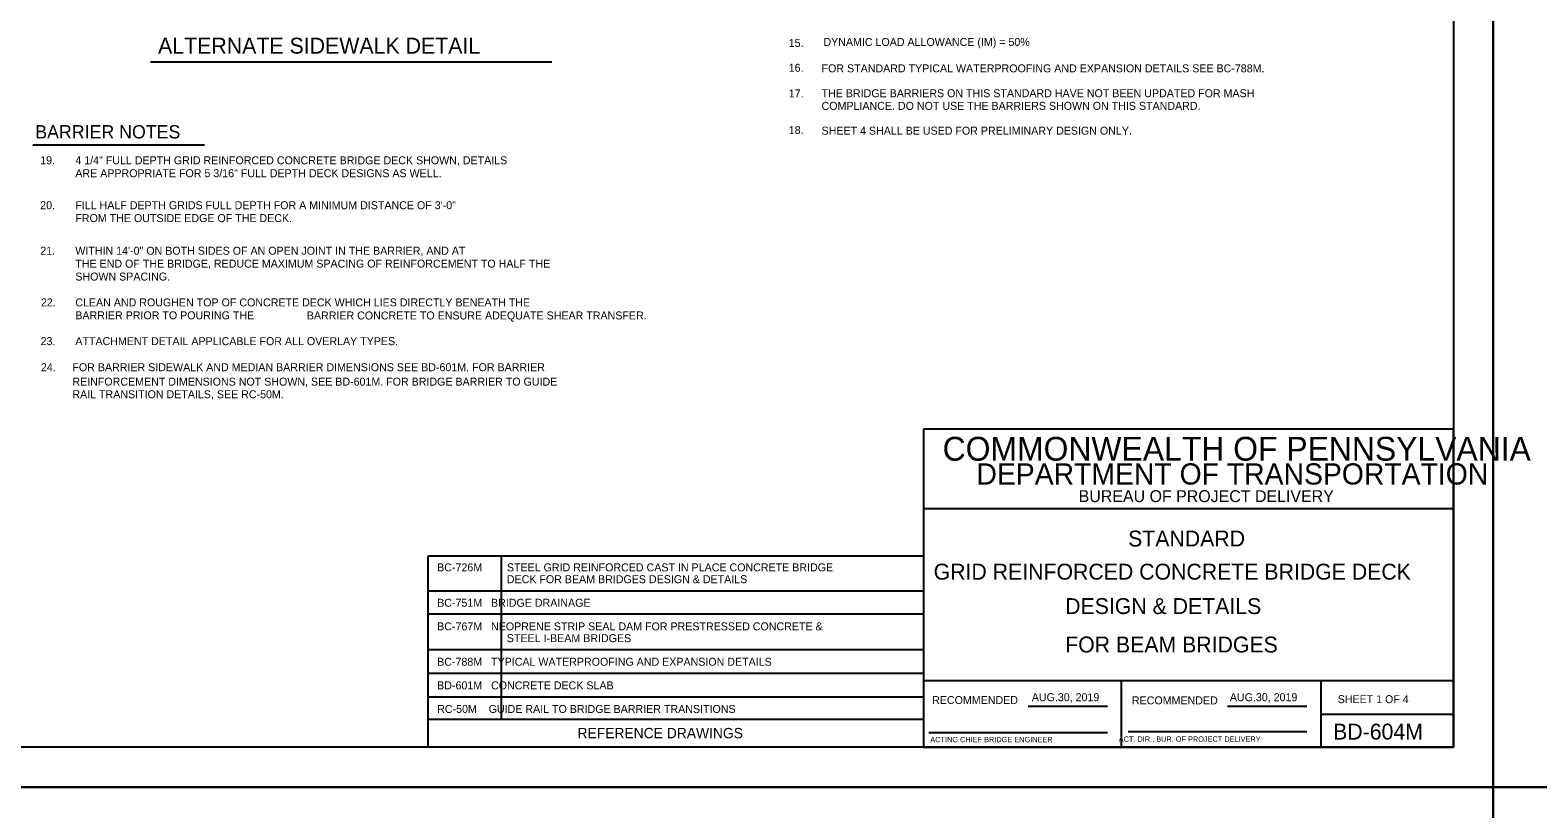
# Model space of a CAD drawing. Extents: x -24512 to -22484, y 4569 to 6351.
# Drawn here: x -23890 to -23322, y 5749 to 6042 of the extents above; entities that cross this region are included whole.
import ezdxf

# ---------------------------------------------------------------- set-up
doc = ezdxf.new("R2010")
doc.units = 0
for name, color, linetype in [('10', 7, 'Continuous'), ('11', 7, 'Continuous'), ('2', 7, 'Continuous'), ('9', 7, 'Continuous'), ('PLT-BNDY', 7, 'Continuous')]:
    doc.layers.add(name, color=color, linetype=linetype)

msp = doc.modelspace()

# ---------------------------------------------------------------- linework, layer by layer
at = {"layer": '10'}
msp.add_line((-23888.51, 5998.81), (-23823.9, 5998.81), dxfattribs=at)
at = {"layer": '11'}
msp.add_line((-23693.17, 6029.98), (-23844.25, 6029.98), dxfattribs=at)
at = {"layer": '2'}
for p, q in [((-23353.75, 6334.63), (-23353.75, 5772.04)), ((-23353.75, 5891.74), (-23553.25, 5891.74)), ((-23553.25, 5891.74), (-23553.25, 5772.04)), ((-23353.75, 5772.04), (-23353.75, 5891.74)), ((-23353.75, 5861.82), (-23553.25, 5861.82)), ((-23739.82, 5844), (-23739.82, 5772.04)), ((-23553.25, 5844), (-23739.82, 5844)), ((-23712.19, 5844), (-23712.19, 5782.47)), ((-23553.25, 5830.82), (-23739.82, 5830.82)), ((-23553.25, 5822.11), (-23739.82, 5822.11)), ((-23553.25, 5808.72), (-23739.82, 5808.72)), ((-23553.25, 5799.79), (-23739.82, 5799.79)), ((-23353.75, 5796.98), (-23553.25, 5796.98)), ((-23478.75, 5772.04), (-23478.75, 5797.04)), ((-23403.63, 5796.98), (-23403.63, 5772.04)), ((-23553.25, 5790.86), (-23739.82, 5790.86)), ((-23513.79, 5787.54), (-23484.02, 5787.54)), ((-23438.79, 5787.54), (-23408.88, 5787.54)), ((-23403.63, 5784.51), (-23353.75, 5784.51)), ((-23553.25, 5782.47), (-23739.82, 5782.47)), ((-23476.13, 5777.92), (-23408.88, 5777.92)), ((-23551.25, 5777.54), (-23484.02, 5777.54)), ((-23353.75, 5772.04), (-24137.79, 5772.04)), ((-23553.25, 5772.04), (-23353.75, 5772.04))]:
    msp.add_line(p, q, dxfattribs=at)
at = {"layer": 'PLT-BNDY'}
for points in [[(-23338.75, 5757.04), (-24179.75, 5757.04), (-24179.75, 6351.04), (-23338.75, 6351.04)], [(-23338.75, 6351.04), (-22497.75, 6351.04), (-22497.75, 5757.04), (-23338.75, 5757.04)], [(-24179.75, 5757.04), (-23338.75, 5757.04), (-23338.75, 5163.04), (-24179.75, 5163.04)], [(-23338.75, 5757.04), (-22497.75, 5757.04), (-22497.75, 5163.04), (-23338.75, 5163.04)]]:
    msp.add_lwpolyline(points, close=True, dxfattribs=at)

# ---------------------------------------------------------------- texts
at = {"layer": '10'}
for s, height, p in [('DYNAMIC LOAD ALLOWANCE (IM) = 50%', 3, (-23590.9, 6036.04)), ('15.', 3, (-23603.96, 6035.66)), ('16.', 3, (-23603.96, 6026.32)), ('FOR STANDARD TYPICAL WATERPROOFING AND EXPANSION DETAILS SEE BC-788M.', 3, (-23591.6, 6026.09)), ('17.', 3, (-23603.96, 6016.66)), ('THE BRIDGE BARRIERS ON THIS STANDARD HAVE NOT BEEN UPDATED FOR MASH', 3, (-23591.6, 6016.73)), ('COMPLIANCE. DO NOT USE THE BARRIERS SHOWN ON THIS STANDARD.', 3, (-23591.6, 6011.98)), ('BARRIER NOTES', 5, (-23887.6, 6001.21)), ('18.', 3, (-23603.96, 6002.86)), ('SHEET 4 SHALL BE USED FOR PRELIMINARY DESIGN ONLY.', 3, (-23591.6, 6002.63)), ('19.', 3, (-23885.74, 5991.48)), ('4 1/4" FULL DEPTH GRID REINFORCED CONCRETE BRIDGE DECK SHOWN, DETAILS', 3, (-23872.52, 5991.48)), ('ARE APPROPRIATE FOR 5 3/16" FULL DEPTH DECK DESIGNS AS WELL.', 3, (-23872.52, 5986.62)), ('20.', 3, (-23885.74, 5974.58)), ('FILL HALF DEPTH GRIDS FULL DEPTH FOR A MINIMUM DISTANCE OF 3\'-0"', 3, (-23872.52, 5974.58)), ('FROM THE OUTSIDE EDGE OF THE DECK.', 3, (-23872.52, 5969.72)), ('21.', 3, (-23885.72, 5957.44)), ('WITHIN 14\'-0" ON BOTH SIDES OF AN OPEN JOINT IN THE BARRIER, AND AT', 3, (-23872.52, 5957.44)), ('THE END OF THE BRIDGE, REDUCE MAXIMUM SPACING OF REINFORCEMENT TO HALF THE', 3, (-23872.52, 5952.58)), ('SHOWN SPACING.', 3, (-23872.52, 5947.72)), ('22.', 3, (-23885.48, 5937.99)), ('CLEAN AND ROUGHEN TOP OF CONCRETE DECK WHICH LIES DIRECTLY BENEATH THE', 3, (-23872.52, 5937.99)), ('BARRIER PRIOR TO POURING THE ', 3, (-23872.52, 5933.13)), ('BARRIER CONCRETE TO ENSURE ADEQUATE SHEAR TRANSFER.', 3, (-23785.38, 5933.07)), ('23.', 3, (-23885.59, 5923.4)), ('ATTACHMENT DETAIL APPLICABLE FOR ALL OVERLAY TYPES.', 3, (-23872.52, 5923.4)), ('24.', 3, (-23885.48, 5913.59)), ('FOR BARRIER SIDEWALK AND MEDIAN BARRIER DIMENSIONS SEE BD-601M. FOR BARRIER', 3, (-23873.63, 5913.59)), ('REINFORCEMENT DIMENSIONS NOT SHOWN, SEE BD-601M. FOR BRIDGE BARRIER TO GUIDE', 3, (-23873.63, 5908.16)), ('RAIL TRANSITION DETAILS, SEE RC-50M.', 3, (-23873.63, 5903.41))]:
    msp.add_text(s, height=height, dxfattribs=at).set_placement(p)
at = {"layer": '11'}
msp.add_text('ALTERNATE SIDEWALK DETAIL', height=6.0008, dxfattribs=at).set_placement((-23841.38, 6033.13))
at = {"layer": '2'}
for s, height, p in [('COMMONWEALTH OF PENNSYLVANIA', 8.9775, (-23546.02, 5879.9)), ('DEPARTMENT OF TRANSPORTATION', 7.9802, (-23533.3, 5870.92)), ('BUREAU OF PROJECT DELIVERY', 4.4888, (-23494.81, 5864.31)), ('STANDARD', 5.985, (-23476.2, 5847.6)), ('GRID REINFORCED CONCRETE BRIDGE DECK', 5.9856, (-23549.41, 5835.13)), ('DESIGN & DETAILS', 5.985, (-23499.89, 5822.17)), ('FOR BEAM BRIDGES', 5.985, (-23499.89, 5807.7)), ('AUG.30, 2019', 3, (-23512.46, 5789.36)), ('AUG.30, 2019', 3, (-23437.91, 5789.36)), ('SHEET 1 OF 4', 2.9925, (-23397.27, 5788.63)), ('BD-604M', 5.985, (-23399.02, 5774.91)), ('ACTING CHIEF BRIDGE ENGINEER', 2.0002, (-23550.66, 5773.92)), ('   ACT. DIR., BUR. OF PROJECT DELIVERY', 2.0002, (-23482.03, 5774.1))]:
    msp.add_text(s, height=height, dxfattribs=at).set_placement(p)
for p in [(-23549.98, 5788.29), (-23474.77, 5788.17)]:
    msp.add_text('RECOMMENDED', height=3, rotation=360, dxfattribs=at).set_placement(p)
at = {"layer": '9'}
for s, height, p in [('BC-726M', 3, (-23736.31, 5838.24)), ('  STEEL GRID REINFORCED CAST IN PLACE CONCRETE BRIDGE', 3, (-23712.31, 5838.24)), ('  DECK FOR BEAM BRIDGES DESIGN & DETAILS', 3, (-23712.31, 5833.79)), ('BC-751M   BRIDGE DRAINAGE', 3, (-23736.31, 5824.91)), ('BC-767M   NEOPRENE STRIP SEAL DAM FOR PRESTRESSED CONCRETE &', 3, (-23736.31, 5816.03)), ('  STEEL I-BEAM BRIDGES', 3, (-23712.31, 5811.59)), ('BC-788M   TYPICAL WATERPROOFING AND EXPANSION DETAILS', 3, (-23736.31, 5802.71)), ('BD-601M   CONCRETE DECK SLAB', 3, (-23736.31, 5793.82)), ('RC-50M    GUIDE RAIL TO BRIDGE BARRIER TRANSITIONS', 3, (-23736.31, 5784.94)), ('REFERENCE DRAWINGS', 3.8998, (-23683.48, 5775.4))]:
    msp.add_text(s, height=height, dxfattribs=at).set_placement(p)

doc.saveas('drawing.dxf')
